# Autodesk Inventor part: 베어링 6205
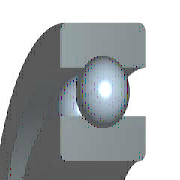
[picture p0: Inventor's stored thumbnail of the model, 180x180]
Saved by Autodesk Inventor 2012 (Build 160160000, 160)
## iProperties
IsCustomPart: 1
Company: 한국ATC센터
Created: 2014-11
Part Number: 베어링 6205
Material: 강, 연강
Description: 깊은 그루브 볼 베어링
Document SubType Name: Modeling
Standard: KS B 2023
Designer: KYOUNG IL JANG
Standards Organization: KS
Language: ko-KR
Size Designation: 6205 - 25 x 52 x 15
Categories: <MemberInstance><Categories><Category DisplayName="샤프트 부품" InternalName="7f7aeb1f-a693-4053-b835-cee3144e0d98" Mnemonic="SHFT"><Category DisplayName="베어링" Inter
Density: 7.86 g/cm^3
Mass: 129.543 g
Surface Area: 107.326 cm^2
Volume: 16.4813 cm^3
Author: KYOUNG IL JANG
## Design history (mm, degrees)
revolve "본체" stored, may be unused: angle "d6" = 90 deg
revolve "볼" stored, may be unused: angle "d7" = 90 deg
pattern_circular "IDS_ARRAYBALL[SIMPL:T]" dims angle "d3" = 360 deg
body "Solid1"
sketch "스케치" dims "d0" = 7.02 (= -0.26 x WD + 0.26 x BD)
  geometry: L1 (3.99, 19.25)-(11.01, 19.25); L2 (7.5, 19.25)-(7.5, 15.74); L3 (7.5, 19.25)-(7.5, 22.76); L4 (4.892, 16.901)-(0, 16.901); L5 (0, 12.5)-(15, 12.5); L6 (4.892, 21.599)-(0, 21.599); L7 (0, 26)-(15, 26); L8 (15, 12.5)-(15, 16.901); L9 (10.108, 16.901)-(15, 16.901); L10 (10.108, 21.599)-(15, 21.599); L11 (15, 26)-(15, 21.599); L12 (-1.4, 0)-(8.4, 0) reference; L13 (0, -0.3)-(0, 5.3) reference
  constraints: 22 end point, 4 point on line, 2 collinear, 2 perpendicular, 2 symmetric about line, 1 midpoint, 1 parallel, 14 other
  dimensions: "d9" = 25 diameter of L5 L12 (= WD); "d11" = 52 diameter of L7 L12 (= BD); "d12" = 15 distance between parallel lines of L8 L13 (= KB); "d13" = 33.802 diameter of L9 L12 (= 0.326 x BD + 0.674 x WD)
fillet "모깎기1" dims "d1" = 1 (= KRS)
other parameters: "WD" = 25 [user parameter; used in 5 equation terms], "BD" = 52 [user parameter; used in 5 equation terms], "KB" = 15 [user parameter; used in 1 equation term], "KRS" = 1 [user parameter; used in 1 equation term], "d4" = 0, "d5" = 0, "d8" = 0, "d14" = 0, "d15" = 0, "BBA" = 0 [user parameter], "BC0" = 7800000 [user parameter], "BC" = 1.4e+07 [user parameter], "BR" = 26 (= 0.5 x BD) [user parameter], "WR" = 12.5 (= 0.5 x WD) [user parameter]
